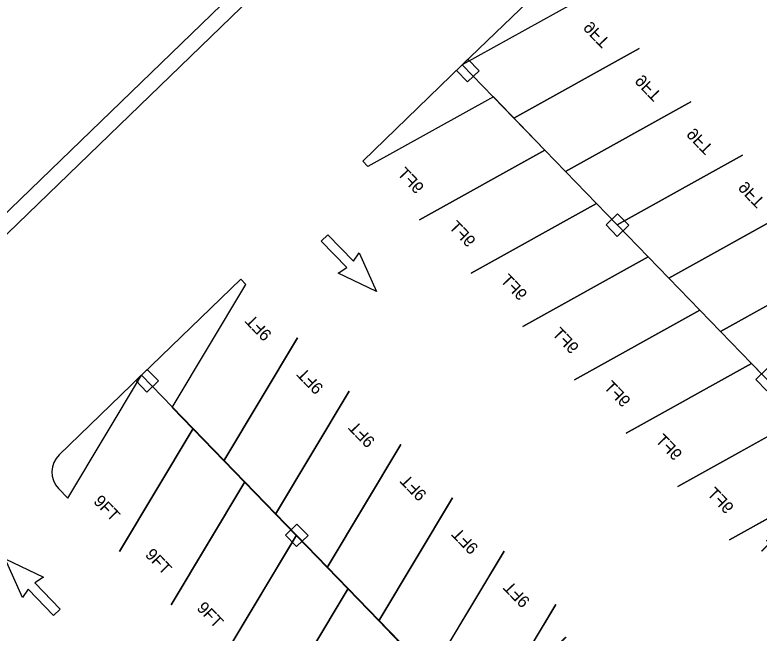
# Model space of a CAD drawing. Extents: x 468143 to 491361, y 1438528 to 1468730.
# Drawn here: x 490323.1 to 490416.5, y 1467542.8 to 1467620.4 of the extents above; entities that cross this region are included whole.
import ezdxf

# ---------------------------------------------------------------- set-up
doc = ezdxf.new("R2010")
doc.units = 0
doc.layers.add('Default', color=7, linetype='Continuous')
doc.layers.add('Xreference_dp', color=7, linetype='Continuous')

# ---------------------------------------------------------------- blocks, each defined once
blk = doc.blocks.new('STALL 9FT-75D')
at = {"layer": 'Default'}
for p, q in [((0, 0), (111.8, 0)), ((111.8, 0), (167.7, -208.6))]:
    blk.add_line(p, q, dxfattribs=at)
blk.add_lwpolyline([(55.9, -208.6), (0, 0)], dxfattribs=at)
blk.add_text('9FT', height=18, dxfattribs=at).set_placement((86.4, -185.9))
blk = doc.blocks.new('arrow-thru')
at = {"layer": 'Default'}
blk.add_lwpolyline([(14.99997, 0), (28.999942, 0), (28.999942, 54.99989), (43.999912, 51.999896), (21.999956, 111.999776), (0, 51.999896), (14.99997, 54.99989)], close=True, dxfattribs=at)
blk = doc.blocks.new('Col 24x24')
at = {"layer": 'Default'}
blk.add_lwpolyline([(-11.999976, -11.999976), (-11.999976, 11.999976), (11.999976, 11.999976), (11.999976, -11.999976), (-11.999976, -11.999976)], dxfattribs=at)
blk.add_lwpolyline([(-11.999976, -11.999976), (11.999976, -11.999976), (11.999976, 11.999976), (-11.999976, 11.999976)], close=True, dxfattribs=at)

msp = doc.modelspace()

# ---------------------------------------------------------------- linework, layer by layer
at = {"layer": 'Xreference_dp'}
for p, q in [((490277.885, 1467550.093), (490407.472, 1467675.481)), ((490277.885, 1467550.093), (490407.472, 1467675.481)), ((490379.215, 1467614.094), (490366.72, 1467602.004)), ((490379.215, 1467614.094), (490366.72, 1467602.004)), ((490367.377, 1467601.326), (490366.72, 1467602.004)), ((490367.377, 1467601.326), (490366.72, 1467602.004)), ((490338.916, 1467575.092), (490351.41, 1467587.182)), ((490338.916, 1467575.092), (490351.41, 1467587.182)), ((490352.067, 1467586.504), (490351.41, 1467587.182)), ((490352.067, 1467586.504), (490351.41, 1467587.182))]:
    msp.add_line(p, q, dxfattribs=at)
for points in [[(490163.784, 1467464.713), (490266.024, 1467563.636), (490277.142, 1467552.145), (490385.499, 1467657)], [(490163.784, 1467464.713), (490266.024, 1467563.636), (490277.142, 1467552.145), (490385.499, 1467657)], [(490389.553, 1467624.097), (490379.214, 1467614.093)], [(490389.553, 1467624.097), (490379.214, 1467614.093)], [(490328.636, 1467565.146), (490338.975, 1467575.149)], [(490328.636, 1467565.146), (490338.975, 1467575.149)], [(490329.72, 1467559.712), (490328.567, 1467560.904)], [(490329.72, 1467559.712), (490328.567, 1467560.904)]]:
    msp.add_lwpolyline(points, dxfattribs=at)
msp.add_arc((490330.723, 1467562.99), 3, 134.05707, 224.05707, dxfattribs=at)
msp.add_arc((490330.723, 1467562.99), 3, 134.05707, 224.05707, dxfattribs=at)

# ---------------------------------------------------------------- block references
for name, p, xscale, yscale, rotation in [('STALL 9FT-75D', (490379.214, 1467614.093), 0.0833307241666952, -0.0833307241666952, -45.94293275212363), ('STALL 9FT-75D', (490379.214, 1467614.093), 0.0833307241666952, -0.0833307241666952, -45.94293275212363), ('STALL 9FT-75D', (490385.693, 1467607.397), 0.0833307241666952, -0.0833307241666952, -45.94293275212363), ('STALL 9FT-75D', (490385.693, 1467607.397), 0.0833307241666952, -0.0833307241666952, -45.94293275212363), ('Col 24x24', (490379.909, 1467613.375), 0.0833307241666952, 0.0833307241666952, 44.062944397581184), ('Col 24x24', (490379.909, 1467613.375), 0.0833307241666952, 0.0833307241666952, 44.062944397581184), ('STALL 9FT-75D', (490389.59, 1467603.372), 0.08333072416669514, -0.08333072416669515, 134.0570672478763), ('STALL 9FT-75D', (490389.59, 1467603.372), 0.08333072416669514, -0.08333072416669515, 134.0570672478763), ('STALL 9FT-75D', (490392.172, 1467600.702), 0.0833307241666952, -0.0833307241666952, -45.94293275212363), ('STALL 9FT-75D', (490392.172, 1467600.702), 0.0833307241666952, -0.0833307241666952, -45.94293275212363), ('STALL 9FT-75D', (490396.068, 1467596.676), 0.08333072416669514, -0.08333072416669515, 134.0570672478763), ('STALL 9FT-75D', (490396.068, 1467596.676), 0.08333072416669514, -0.08333072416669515, 134.0570672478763), ('STALL 9FT-75D', (490398.651, 1467594.006), 0.0833307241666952, -0.0833307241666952, -45.94293275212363), ('STALL 9FT-75D', (490398.651, 1467594.006), 0.0833307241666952, -0.0833307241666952, -45.94293275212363), ('STALL 9FT-75D', (490402.547, 1467589.98), 0.08333072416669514, -0.08333072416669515, 134.0570672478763), ('STALL 9FT-75D', (490402.547, 1467589.98), 0.08333072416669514, -0.08333072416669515, 134.0570672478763), ('STALL 9FT-75D', (490405.13, 1467587.31), 0.0833307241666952, -0.0833307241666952, -45.94293275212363), ('STALL 9FT-75D', (490405.13, 1467587.31), 0.0833307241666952, -0.0833307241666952, -45.94293275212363), ('Col 24x24', (490398.686, 1467593.974), 0.0833307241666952, 0.0833307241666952, 44.062944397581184), ('Col 24x24', (490398.686, 1467593.974), 0.0833307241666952, 0.0833307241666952, 44.062944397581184), ('arrow-thru', (490360.629, 1467591.073), 0.08333072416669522, -0.08333072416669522, 44.057067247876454), ('arrow-thru', (490360.629, 1467591.073), 0.08333072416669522, -0.08333072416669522, 44.057067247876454), ('STALL 9FT-75D', (490409.026, 1467583.285), 0.08333072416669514, -0.08333072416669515, 134.0570672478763), ('STALL 9FT-75D', (490409.026, 1467583.285), 0.08333072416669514, -0.08333072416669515, 134.0570672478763), ('STALL 9FT-75D', (490411.609, 1467580.614), 0.0833307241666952, -0.0833307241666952, -45.94293275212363), ('STALL 9FT-75D', (490411.609, 1467580.614), 0.0833307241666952, -0.0833307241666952, -45.94293275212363), ('STALL 9FT-75D', (490349.291, 1467564.37), 0.0833307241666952, 0.08333072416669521, 134.05706724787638), ('STALL 9FT-75D', (490349.291, 1467564.37), 0.0833307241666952, 0.08333072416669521, 134.05706724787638), ('STALL 9FT-75D', (490415.505, 1467576.589), 0.08333072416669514, -0.08333072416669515, 134.0570672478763), ('STALL 9FT-75D', (490415.505, 1467576.589), 0.08333072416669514, -0.08333072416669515, 134.0570672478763), ('STALL 9FT-75D', (490355.77, 1467557.674), 0.0833307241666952, 0.08333072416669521, 134.05706724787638), ('STALL 9FT-75D', (490355.77, 1467557.674), 0.0833307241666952, 0.08333072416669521, 134.05706724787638), ('STALL 9FT-75D', (490421.984, 1467569.893), 0.08333072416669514, -0.08333072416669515, 134.0570672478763), ('STALL 9FT-75D', (490421.984, 1467569.893), 0.08333072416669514, -0.08333072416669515, 134.0570672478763), ('Col 24x24', (490339.67, 1467574.431), 0.0833307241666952, 0.0833307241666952, 44.062944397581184), ('Col 24x24', (490339.67, 1467574.431), 0.0833307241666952, 0.0833307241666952, 44.062944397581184), ('Col 24x24', (490417.462, 1467574.573), 0.0833307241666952, 0.0833307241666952, 44.062944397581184), ('Col 24x24', (490417.462, 1467574.573), 0.0833307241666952, 0.0833307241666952, 44.062944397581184), ('STALL 9FT-75D', (490338.975, 1467575.149), 0.08333072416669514, 0.08333072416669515, -45.942932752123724), ('STALL 9FT-75D', (490338.975, 1467575.149), 0.08333072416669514, 0.08333072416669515, -45.942932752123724), ('STALL 9FT-75D', (490362.249, 1467550.979), 0.0833307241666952, 0.08333072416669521, 134.05706724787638), ('STALL 9FT-75D', (490362.249, 1467550.979), 0.0833307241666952, 0.08333072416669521, 134.05706724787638), ('STALL 9FT-75D', (490428.463, 1467563.197), 0.08333072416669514, -0.08333072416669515, 134.0570672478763), ('STALL 9FT-75D', (490428.463, 1467563.197), 0.08333072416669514, -0.08333072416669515, 134.0570672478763), ('STALL 9FT-75D', (490345.454, 1467568.454), 0.08333072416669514, 0.08333072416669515, -45.942932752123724), ('STALL 9FT-75D', (490345.454, 1467568.454), 0.08333072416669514, 0.08333072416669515, -45.942932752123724), ('STALL 9FT-75D', (490368.727, 1467544.283), 0.0833307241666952, 0.08333072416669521, 134.05706724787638), ('STALL 9FT-75D', (490368.727, 1467544.283), 0.0833307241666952, 0.08333072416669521, 134.05706724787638), ('STALL 9FT-75D', (490434.942, 1467556.502), 0.08333072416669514, -0.08333072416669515, 134.0570672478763), ('STALL 9FT-75D', (490434.942, 1467556.502), 0.08333072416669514, -0.08333072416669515, 134.0570672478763), ('STALL 9FT-75D', (490351.933, 1467561.758), 0.08333072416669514, 0.08333072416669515, -45.942932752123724), ('STALL 9FT-75D', (490351.933, 1467561.758), 0.08333072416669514, 0.08333072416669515, -45.942932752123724), ('STALL 9FT-75D', (490375.206, 1467537.587), 0.0833307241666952, 0.08333072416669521, 134.05706724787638), ('STALL 9FT-75D', (490375.206, 1467537.587), 0.0833307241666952, 0.08333072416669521, 134.05706724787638), ('Col 24x24', (490358.447, 1467555.03), 0.0833307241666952, 0.0833307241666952, 44.062944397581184), ('Col 24x24', (490358.447, 1467555.03), 0.0833307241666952, 0.0833307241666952, 44.062944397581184), ('STALL 9FT-75D', (490358.412, 1467555.062), 0.08333072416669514, 0.08333072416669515, -45.942932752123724), ('STALL 9FT-75D', (490358.412, 1467555.062), 0.08333072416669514, 0.08333072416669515, -45.942932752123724), ('arrow-thru', (490329.67, 1467546.648), 0.0833307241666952, -0.08333072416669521, -135.9429327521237), ('arrow-thru', (490329.67, 1467546.648), 0.0833307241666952, -0.08333072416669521, -135.9429327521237), ('STALL 9FT-75D', (490381.685, 1467530.891), 0.0833307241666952, 0.08333072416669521, 134.05706724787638), ('STALL 9FT-75D', (490381.685, 1467530.891), 0.0833307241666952, 0.08333072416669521, 134.05706724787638), ('STALL 9FT-75D', (490364.891, 1467548.366), 0.08333072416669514, 0.08333072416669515, -45.942932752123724), ('STALL 9FT-75D', (490364.891, 1467548.366), 0.08333072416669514, 0.08333072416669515, -45.942932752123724), ('STALL 9FT-75D', (490388.164, 1467524.196), 0.0833307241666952, 0.08333072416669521, 134.05706724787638), ('STALL 9FT-75D', (490388.164, 1467524.196), 0.0833307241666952, 0.08333072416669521, 134.05706724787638)]:
    msp.add_blockref(name, p, dxfattribs=dict(at, xscale=xscale, yscale=yscale, rotation=rotation))

doc.saveas('drawing.dxf')
